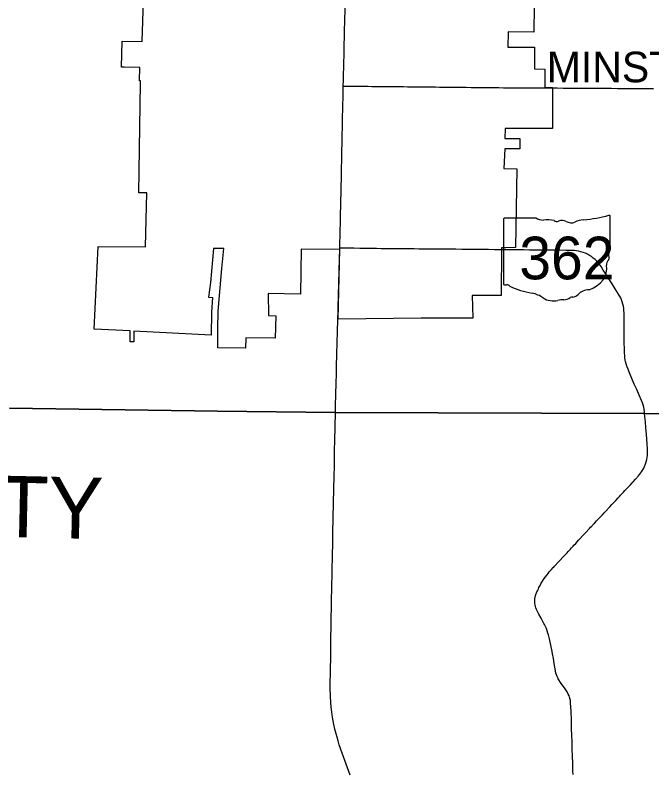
# Model space of a CAD drawing. Extents: x 0 to 34, y 0 to 22.
# Drawn here: x 4.4563 to 4.6233, y 18.7139 to 18.9124 of the extents above; entities that cross this region are included whole.
import ezdxf

# ---------------------------------------------------------------- set-up
doc = ezdxf.new("R2010")
doc.units = 0
for name, color, linetype in [('GM_X_Corporation', 7, 'Continuous'), ('GM_X_Corporation_Text', 7, 'Continuous'), ('GM_X_County', 7, 'Continuous'), ('GM_X_County_Text', 7, 'Continuous'), ('GM_X_State_Location', 7, 'Continuous'), ('GM_X_State_Route', 7, 'Continuous'), ('GM_X_State_Shield', 7, 'Continuous')]:
    doc.layers.add(name, color=color, linetype=linetype)

msp = doc.modelspace()

# ---------------------------------------------------------------- linework, layer by layer
at = {"layer": 'GM_X_Corporation'}
msp.add_lwpolyline([(4.59243, 18.91472), (4.59232, 18.90789), (4.5856, 18.90794), (4.58554, 18.90395), (4.59247, 18.90395), (4.59248, 18.89823), (4.59525, 18.89822), (4.59525, 18.89338), (4.59726, 18.89338), (4.59726, 18.88265), (4.58482, 18.88265), (4.58475, 18.88002), (4.58868, 18.88003), (4.58864, 18.87725), (4.58468, 18.87725), (4.58444, 18.87215), (4.58784, 18.87206), (4.58749, 18.8514), (4.585, 18.85134), (4.58383, 18.85131), (4.58383, 18.85091), (4.58373, 18.8388), (4.57614, 18.83882), (4.57631, 18.83288), (4.56274, 18.83286), (4.54103, 18.83265), (4.54145, 18.85088), (4.5313, 18.85096), (4.53111, 18.83918), (4.52268, 18.83937), (4.52275, 18.83355), (4.52464, 18.83352), (4.52447, 18.82762), (4.51682, 18.82775), (4.5167, 18.82505), (4.50945, 18.82514), (4.50943, 18.82991), (4.50951, 18.83476), (4.51045, 18.84593), (4.51099, 18.85114), (4.50828, 18.85116), (4.50756, 18.84225), (4.50699, 18.83837), (4.50804, 18.8383), (4.50778, 18.83444), (4.50771, 18.82845), (4.48738, 18.82948), (4.48738, 18.82664), (4.48642, 18.82666), (4.48642, 18.82953), (4.47699, 18.83001), (4.47809, 18.85169), (4.49045, 18.8516), (4.49084, 18.86575), (4.48868, 18.86575), (4.48916, 18.89455), (4.48918, 18.89509), (4.4889, 18.89509), (4.48899, 18.89864), (4.48484, 18.8987), (4.48414, 18.8987), (4.48431, 18.90554), (4.48956, 18.90543), (4.48995, 18.91608)], dxfattribs=at)
at = {"layer": 'GM_X_County'}
for points in [[(4.45476, 18.80929), (4.50934, 18.80852), (4.54026, 18.80814), (4.62135, 18.80787), (4.65288, 18.80729)], [(4.65288, 18.80729), (4.62135, 18.80787), (4.54026, 18.80814), (4.50934, 18.80852), (4.45476, 18.80929)]]:
    msp.add_lwpolyline(points, dxfattribs=at)
at = {"layer": 'GM_X_State_Route'}
for p, q in [((4.54141, 18.85042), (4.54144, 18.85126)), ((4.58747, 18.85079), (4.58739, 18.85079))]:
    msp.add_line(p, q, dxfattribs=at)
for points in [[(4.54269, 18.90795), (4.54271, 18.909), (4.54274, 18.91004), (4.54277, 18.91163), (4.54281, 18.91321), (4.54285, 18.91479), (4.54289, 18.91637), (4.54293, 18.91795), (4.54296, 18.91953), (4.54299, 18.92082), (4.54302, 18.9221)], [(4.54235, 18.89376), (4.54239, 18.89534), (4.54243, 18.89692), (4.54246, 18.8985), (4.5425, 18.90008), (4.54254, 18.90166), (4.54258, 18.90325), (4.54261, 18.90483), (4.54265, 18.90639), (4.54269, 18.90795)], [(4.54144, 18.85126), (4.54147, 18.85284), (4.54151, 18.85442), (4.54154, 18.85601), (4.54158, 18.85759), (4.54161, 18.85917), (4.54165, 18.86075), (4.54167, 18.86176), (4.54169, 18.86278), (4.54172, 18.86411), (4.54175, 18.86544), (4.54178, 18.86658), (4.5418, 18.86772), (4.54184, 18.8693), (4.54187, 18.87088), (4.5419, 18.87246), (4.54193, 18.87404), (4.54197, 18.87562), (4.542, 18.8772), (4.54203, 18.87838), (4.54205, 18.87955), (4.54208, 18.88114), (4.54212, 18.88272), (4.54215, 18.8843), (4.54218, 18.88588), (4.54222, 18.88746), (4.54225, 18.88904), (4.54228, 18.89062), (4.54232, 18.89219), (4.54235, 18.89376)], [(4.54235, 18.89376), (4.54339, 18.89375), (4.54497, 18.89373), (4.54655, 18.89371), (4.54772, 18.8937), (4.54888, 18.89369), (4.54983, 18.89368), (4.55077, 18.89367), (4.55236, 18.89366), (4.55394, 18.89364), (4.55552, 18.89362), (4.5571, 18.89361), (4.55815, 18.8936), (4.55919, 18.89359), (4.56078, 18.89357), (4.56236, 18.89356), (4.56394, 18.89354), (4.56552, 18.89352), (4.56655, 18.89351), (4.56758, 18.8935), (4.56916, 18.89349), (4.57074, 18.89347), (4.57198, 18.89346), (4.57322, 18.89345), (4.57456, 18.89343), (4.5759, 18.89342), (4.57731, 18.8934), (4.57872, 18.89339), (4.5803, 18.89337), (4.58188, 18.89336), (4.58311, 18.89335), (4.58434, 18.89333), (4.58517, 18.89333)], [(4.58517, 18.89333), (4.58592, 18.89332), (4.5875, 18.89331), (4.58909, 18.8933), (4.59067, 18.89329), (4.59225, 18.89328), (4.59351, 18.89328), (4.59477, 18.89327)], [(4.59477, 18.89327), (4.59582, 18.89326), (4.59687, 18.89325)], [(4.59687, 18.89325), (4.59845, 18.89325), (4.60003, 18.89324), (4.60161, 18.89323), (4.60319, 18.89322), (4.60478, 18.89321), (4.60586, 18.8932)], [(4.60586, 18.8932), (4.60636, 18.8932), (4.60794, 18.89319), (4.60952, 18.89318), (4.6111, 18.89317), (4.61269, 18.89316), (4.61427, 18.89315), (4.61585, 18.89314), (4.61743, 18.89313), (4.61901, 18.89312), (4.6206, 18.89311), (4.62218, 18.8931), (4.62376, 18.89309)], [(4.55238, 18.85111), (4.5523, 18.85111), (4.55106, 18.85113), (4.54983, 18.85114), (4.54825, 18.85116), (4.54666, 18.85118), (4.54508, 18.85121), (4.5435, 18.85123), (4.54247, 18.85125), (4.54144, 18.85126)], [(4.58411, 18.85082), (4.58358, 18.85083), (4.58199, 18.85084), (4.58041, 18.85086), (4.57883, 18.85087), (4.57725, 18.85089), (4.57613, 18.8509), (4.575, 18.85091), (4.57342, 18.85092), (4.57184, 18.85094), (4.57026, 18.85095), (4.56867, 18.85096), (4.56762, 18.85097), (4.56657, 18.85098), (4.56499, 18.851), (4.5634, 18.85101), (4.56218, 18.85102), (4.56096, 18.85103), (4.55938, 18.85105), (4.5578, 18.85106), (4.55663, 18.85107), (4.55546, 18.85108), (4.55388, 18.8511), (4.55238, 18.85111)], [(4.54093, 18.8329), (4.54098, 18.83448), (4.54101, 18.83553), (4.54104, 18.83658), (4.54108, 18.83816), (4.54112, 18.83974), (4.54116, 18.84132), (4.54121, 18.84291), (4.54125, 18.84449), (4.54129, 18.84607), (4.54134, 18.84765), (4.54138, 18.84923), (4.54141, 18.85025), (4.54141, 18.85042)], [(4.58739, 18.85079), (4.58589, 18.85081), (4.585, 18.85082), (4.58411, 18.85082)], [(4.62137, 18.80782), (4.62132, 18.80834), (4.62125, 18.80894), (4.62114, 18.80954), (4.62099, 18.81013), (4.6208, 18.81071), (4.62058, 18.81127), (4.61994, 18.81272), (4.61931, 18.81417), (4.61868, 18.81562), (4.61804, 18.81707), (4.6174, 18.81858), (4.61695, 18.8197), (4.61675, 18.82027), (4.61655, 18.82095), (4.6164, 18.82148), (4.61632, 18.82191), (4.61624, 18.82249), (4.61619, 18.82308), (4.61615, 18.82379), (4.61612, 18.82459), (4.61604, 18.82664), (4.61603, 18.82822), (4.61602, 18.8298), (4.61602, 18.83138), (4.61601, 18.83285), (4.616, 18.83432), (4.61598, 18.83489), (4.61592, 18.83546), (4.61583, 18.83603), (4.6157, 18.83659), (4.61554, 18.83715), (4.61534, 18.83769), (4.61511, 18.83822), (4.61484, 18.83873), (4.61455, 18.83922), (4.6137, 18.84056), (4.61284, 18.84189), (4.61199, 18.84322), (4.61114, 18.84456), (4.61055, 18.84548), (4.60996, 18.84641), (4.60961, 18.84691), (4.60923, 18.84739), (4.60882, 18.84784), (4.60839, 18.84827), (4.60792, 18.84866), (4.60743, 18.84902), (4.60692, 18.84935), (4.60639, 18.84965), (4.60584, 18.84991), (4.60527, 18.85013), (4.60469, 18.85032), (4.60409, 18.85046), (4.60349, 18.85057), (4.60289, 18.85063), (4.60228, 18.85066), (4.6007, 18.85067), (4.59912, 18.85069), (4.59753, 18.8507), (4.59595, 18.85072), (4.59437, 18.85073), (4.59279, 18.85074), (4.5912, 18.85076), (4.58962, 18.85077), (4.58855, 18.85078), (4.58747, 18.85079)], [(4.54078, 18.82708), (4.54082, 18.82867), (4.54086, 18.83025), (4.5409, 18.83157), (4.54093, 18.8329)], [(4.54048, 18.81629), (4.54053, 18.81788), (4.54057, 18.81946), (4.54061, 18.82104), (4.54066, 18.82262), (4.5407, 18.8242), (4.54074, 18.82564), (4.54078, 18.82708)], [(4.54028, 18.8081), (4.54031, 18.80901), (4.54034, 18.81059), (4.54038, 18.81217), (4.54042, 18.81375), (4.54045, 18.81502), (4.54048, 18.81629)], [(4.53897, 18.7345), (4.53895, 18.73501), (4.53894, 18.73697), (4.53897, 18.74018), (4.53904, 18.74461), (4.53911, 18.74873), (4.53918, 18.75226), (4.5393, 18.75901), (4.53934, 18.76197), (4.53942, 18.7664), (4.53952, 18.77088), (4.53958, 18.77362), (4.53964, 18.77663), (4.53981, 18.78449), (4.53996, 18.79154), (4.53997, 18.79192), (4.54002, 18.79361), (4.54005, 18.79603), (4.54006, 18.79645), (4.54007, 18.79814), (4.54012, 18.80078), (4.54028, 18.8081)], [(4.62212, 18.79683), (4.62215, 18.79702), (4.62218, 18.79765), (4.62217, 18.79812), (4.62216, 18.79865), (4.62209, 18.79985), (4.62189, 18.80243), (4.62175, 18.80411), (4.62159, 18.80574), (4.62137, 18.80782)], [(4.61075, 18.7818), (4.6109, 18.78195), (4.61115, 18.78222), (4.61226, 18.78341), (4.61281, 18.78398), (4.61352, 18.78476), (4.61384, 18.78511), (4.61445, 18.78577), (4.61478, 18.78611), (4.61509, 18.78647), (4.61553, 18.78693), (4.61582, 18.78723), (4.61622, 18.78765), (4.6177, 18.78922), (4.61813, 18.78969), (4.61841, 18.79), (4.61901, 18.79066), (4.6198, 18.79158), (4.62006, 18.79191), (4.62055, 18.79259), (4.62088, 18.79312), (4.62114, 18.79358), (4.62134, 18.794), (4.62162, 18.79468), (4.6218, 18.79523), (4.62195, 18.79579), (4.62206, 18.79635), (4.62212, 18.79683)], [(4.60264, 18.71321), (4.6026, 18.71405), (4.60253, 18.71621), (4.6024, 18.71985), (4.60236, 18.72175), (4.60225, 18.72528), (4.60218, 18.72744), (4.60209, 18.72976), (4.60205, 18.73087), (4.60198, 18.73197), (4.60191, 18.73259), (4.60181, 18.73311), (4.60177, 18.7333), (4.60171, 18.73348), (4.60158, 18.73385), (4.60137, 18.73432), (4.60106, 18.73487), (4.60054, 18.73566), (4.59933, 18.73738), (4.59892, 18.738), (4.59875, 18.73827), (4.59859, 18.73854), (4.59841, 18.73893), (4.59824, 18.73937), (4.59811, 18.73978), (4.59797, 18.7404), (4.59767, 18.74228), (4.59745, 18.74363), (4.59724, 18.74488), (4.59713, 18.74544), (4.5964, 18.74879), (4.59615, 18.74982), (4.59604, 18.75027), (4.59584, 18.75092), (4.59563, 18.75146), (4.59544, 18.75189), (4.59509, 18.75257), (4.59496, 18.75282), (4.59425, 18.75418), (4.59366, 18.7553), (4.59307, 18.75648), (4.59289, 18.75693), (4.59277, 18.75728), (4.59266, 18.7577), (4.59259, 18.75806), (4.59256, 18.75838), (4.59256, 18.75891), (4.59259, 18.75929), (4.59266, 18.75971), (4.59276, 18.76018), (4.59284, 18.76043), (4.59299, 18.76083), (4.59312, 18.76112), (4.59326, 18.76141), (4.59352, 18.76193), (4.59366, 18.76221), (4.594, 18.76281), (4.5942, 18.76318), (4.59488, 18.76431), (4.59532, 18.76496), (4.59579, 18.7656), (4.59605, 18.76593), (4.59638, 18.76633), (4.59662, 18.7666), (4.59672, 18.76672), (4.59696, 18.76699), (4.59741, 18.76748), (4.59755, 18.76762), (4.59778, 18.76788), (4.59784, 18.76794), (4.59881, 18.76897), (4.59909, 18.76927), (4.60014, 18.77039), (4.60082, 18.77112), (4.60103, 18.77135), (4.60131, 18.77166), (4.60142, 18.77177), (4.60162, 18.77199), (4.60194, 18.77231), (4.60225, 18.77265), (4.60238, 18.7728), (4.60265, 18.7731), (4.60286, 18.77333), (4.60333, 18.77382), (4.60408, 18.77463), (4.60543, 18.77611), (4.6059, 18.77662), (4.60693, 18.77774), (4.60722, 18.77804), (4.60751, 18.77835), (4.60766, 18.7785), (4.60784, 18.77868), (4.60812, 18.779), (4.6082, 18.77907), (4.60841, 18.7793), (4.6088, 18.77973), (4.60999, 18.781), (4.61032, 18.78134), (4.61075, 18.7818)], [(4.54412, 18.71303), (4.54204, 18.71878), (4.5413, 18.72103), (4.54101, 18.722), (4.54071, 18.72302), (4.54048, 18.72384), (4.54017, 18.72507), (4.5399, 18.72636), (4.53954, 18.72828), (4.53933, 18.72969), (4.53919, 18.73085), (4.53908, 18.73216), (4.53899, 18.73364), (4.53897, 18.7345)]]:
    msp.add_lwpolyline(points, dxfattribs=at)
at = {"layer": 'GM_X_State_Shield'}
for p, q in [((4.59283, 18.85915), (4.58464, 18.85915)), ((4.61233, 18.85069), (4.61233, 18.85957)), ((4.58436, 18.85886), (4.58436, 18.84188)), ((4.61233, 18.85069), (4.61233, 18.85069))]:
    msp.add_line(p, q, dxfattribs=at)
for centre, major_axis, start_param, end_param in [((4.58468, 18.8589), (0.000324, 0), 1.712693, 3.28349), ((4.59478, 18.86113), (0.00314, 0), 4.042523, 4.731795), ((4.60237, 18.88231), (0.02966, 0), 4.814394, 5.042369), ((4.61202, 18.85961), (0.000311, 0), 6.141152, 7.989035), ((4.59582, 18.84962), (0.01128, 0), 1.404758, 1.657858), ((4.59838, 18.85899), (0.000907, 0), 3.836095, 5.185415), ((4.59971, 18.85702), (0.00189, 0), 0.950623, 2.079405), ((4.60215, 18.85972), (0.00227, 0), 4.081561, 5.145723), ((4.60615, 18.85397), (0.00597, 0), 1.699011, 2.107814), ((4.61226, 18.85004), (0.000482, 0), 1.883978, 3.671073), ((4.6092, 18.84891), (0.00289, 0), 5.934695, 6.695948), ((4.612, 18.85066), (0.000333, 0), 5.05454, 6.418171), ((4.61345, 18.84697), (0.0021, 0), 2.387724, 3.262537), ((4.60403, 18.84584), (0.00742, 0), 5.101752, 6.440018), ((4.58468, 18.84184), (0.000327, 0), 3.00124, 4.508301), ((4.58473, 18.84358), (0.00249, 0), 4.665946, 4.897461), ((4.58524, 18.8409), (0.0009, 0), 0.519207, 1.627899), ((4.5966, 18.85616), (0.02142, 0), 4.195997, 4.488961), ((4.59022, 18.83425), (0.0067, 0), 0.823519, 1.323587), ((4.60716, 18.83711), (0.00406, 0), 1.647645, 2.488434), ((4.59746, 18.84081), (0.00425, 0), 4.026481, 4.996735), ((4.59992, 18.83494), (0.00349, 0), 1.495662, 1.94098), ((4.60023, 18.83954), (0.00227, 0), 4.691044, 5.507374), ((4.60228, 18.8379), (0.000638, 0), 1.147584, 2.315152), ((4.60201, 18.84023), (0.0024, 0), 4.937069, 5.64225)]:
    msp.add_ellipse(centre, major_axis=major_axis, ratio=0.8, start_param=start_param, end_param=end_param, dxfattribs=at)

# ---------------------------------------------------------------- texts
at = {"layer": 'GM_X_Corporation_Text'}
msp.add_text('MINSTER', height=0.008037, rotation=0, dxfattribs=at).set_placement((4.59572, 18.89474))
at = {"layer": 'GM_X_County_Text'}
msp.add_text('SHELBY COUNTY', height=0.016074, rotation=358.7591, dxfattribs=at).set_placement((4.29768, 18.77887))
at = {"layer": 'GM_X_State_Location'}
for s in ['s', 'r']:
    msp.add_text(s, height=0.0000161, dxfattribs=at).set_placement((4.59803, 18.84924))
msp.add_text('362', height=0.0000161, rotation=0, dxfattribs=at).set_placement((4.59236, 18.84807))
at = {"layer": 'GM_X_State_Shield'}
msp.add_text('362', height=0.011189, dxfattribs=at).set_placement((4.58852, 18.84307))

doc.saveas('drawing.dxf')
